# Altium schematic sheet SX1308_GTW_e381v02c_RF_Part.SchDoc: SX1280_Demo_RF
size A2; DrawnBy: Erik Fountain; DocumentNumber: 2; SheetNumber: 2; SheetTotal: 5; PageSetup: Record=PageOptions|CenterHorizontal=True|CenterVertical=True|PrintScale=0.47|XCorrection=1.00|YCorrection=1.00|PrintKind=0|BorderSize=5000000|LeftOffset=0|BottomOffset=0|Orientation=2|PaperLength=1000|PaperWidth=1000|Scale=100|PaperSource=7|PrintQuality=-4|MediaType=1|DitherType=10|PaperKind=Letter|PrintScaleMode=1
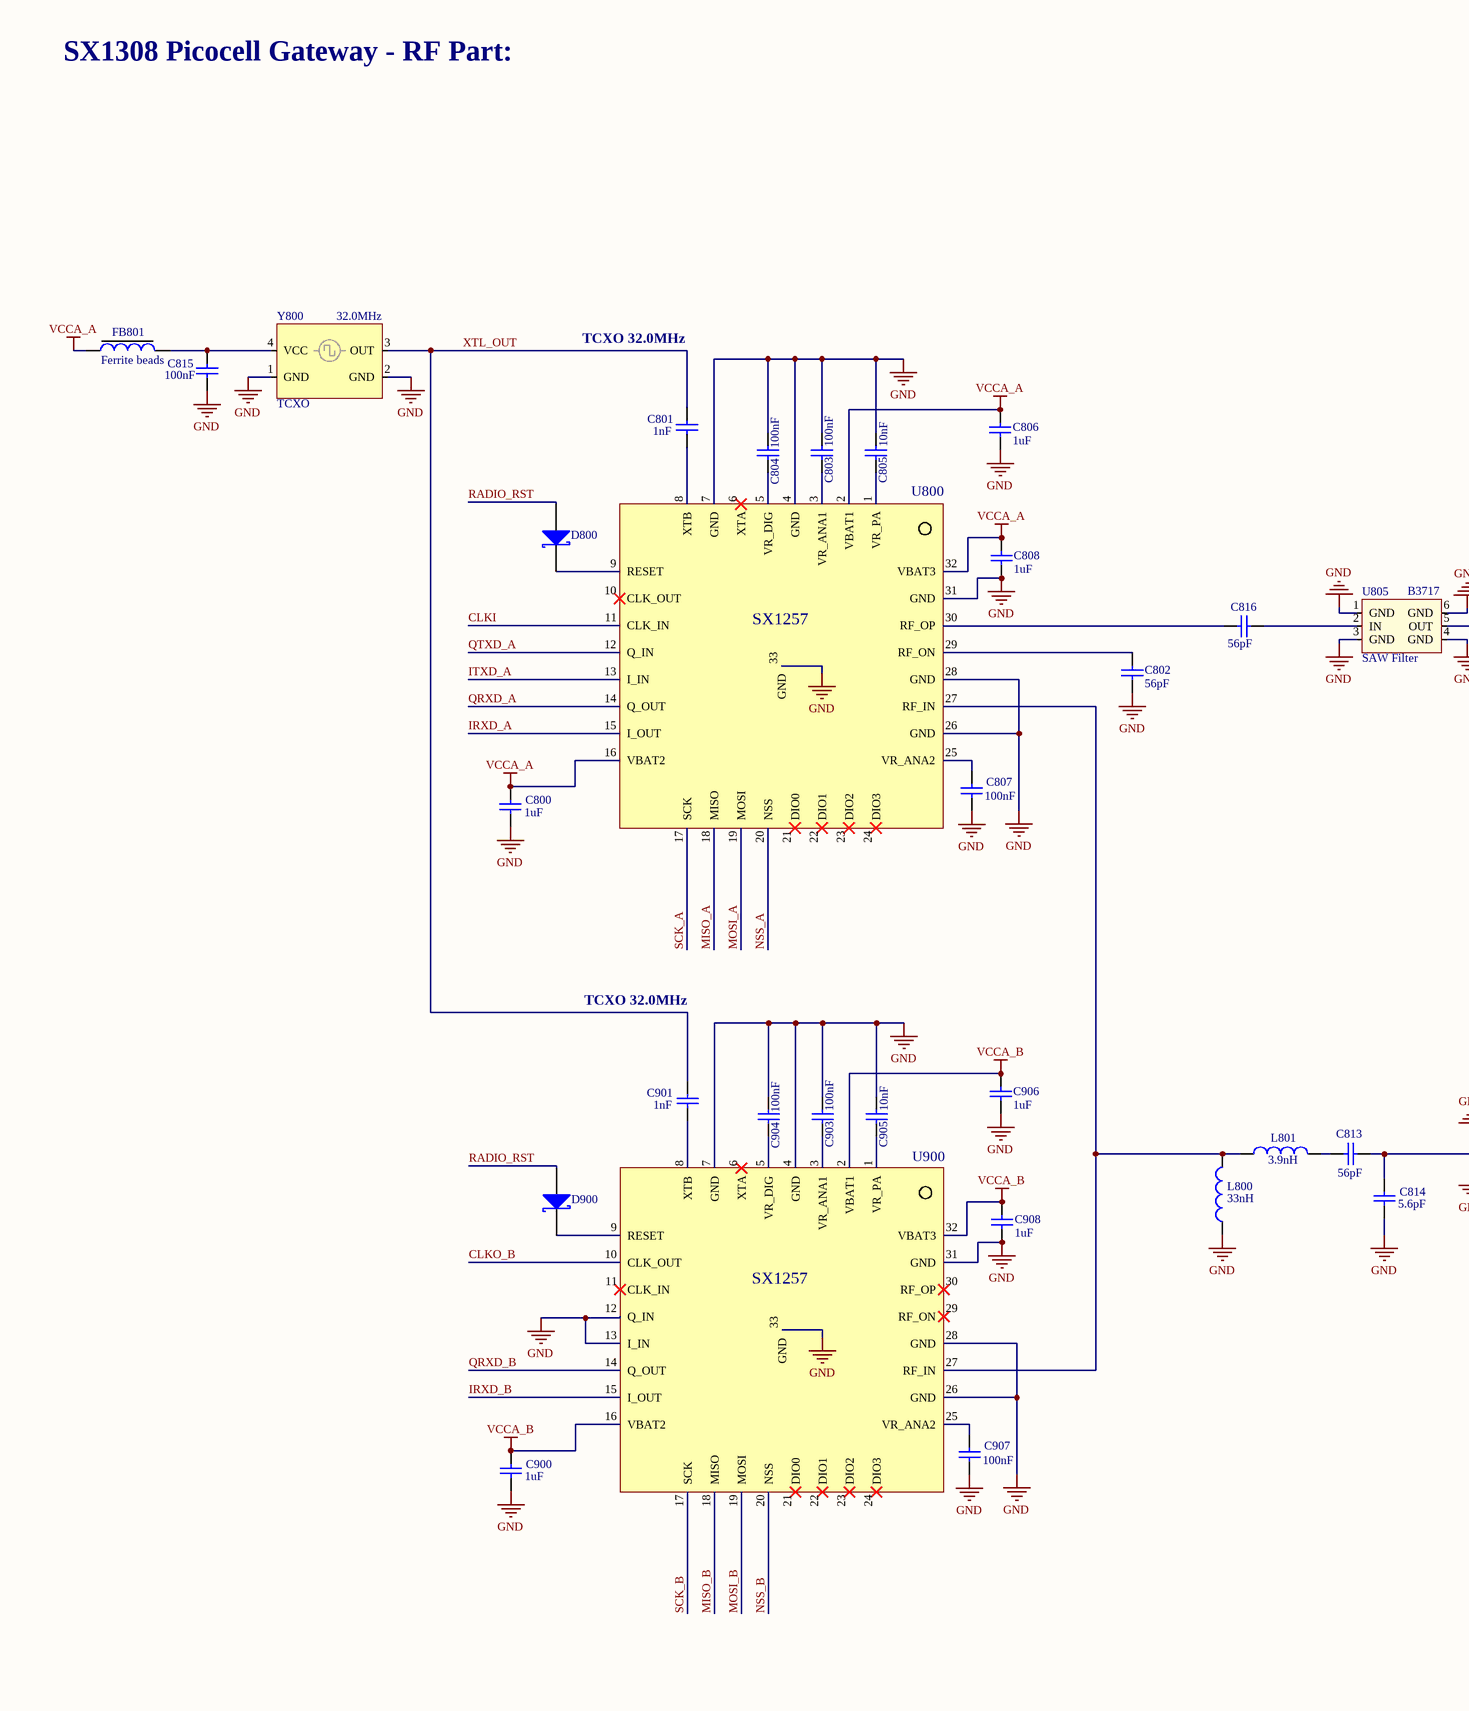
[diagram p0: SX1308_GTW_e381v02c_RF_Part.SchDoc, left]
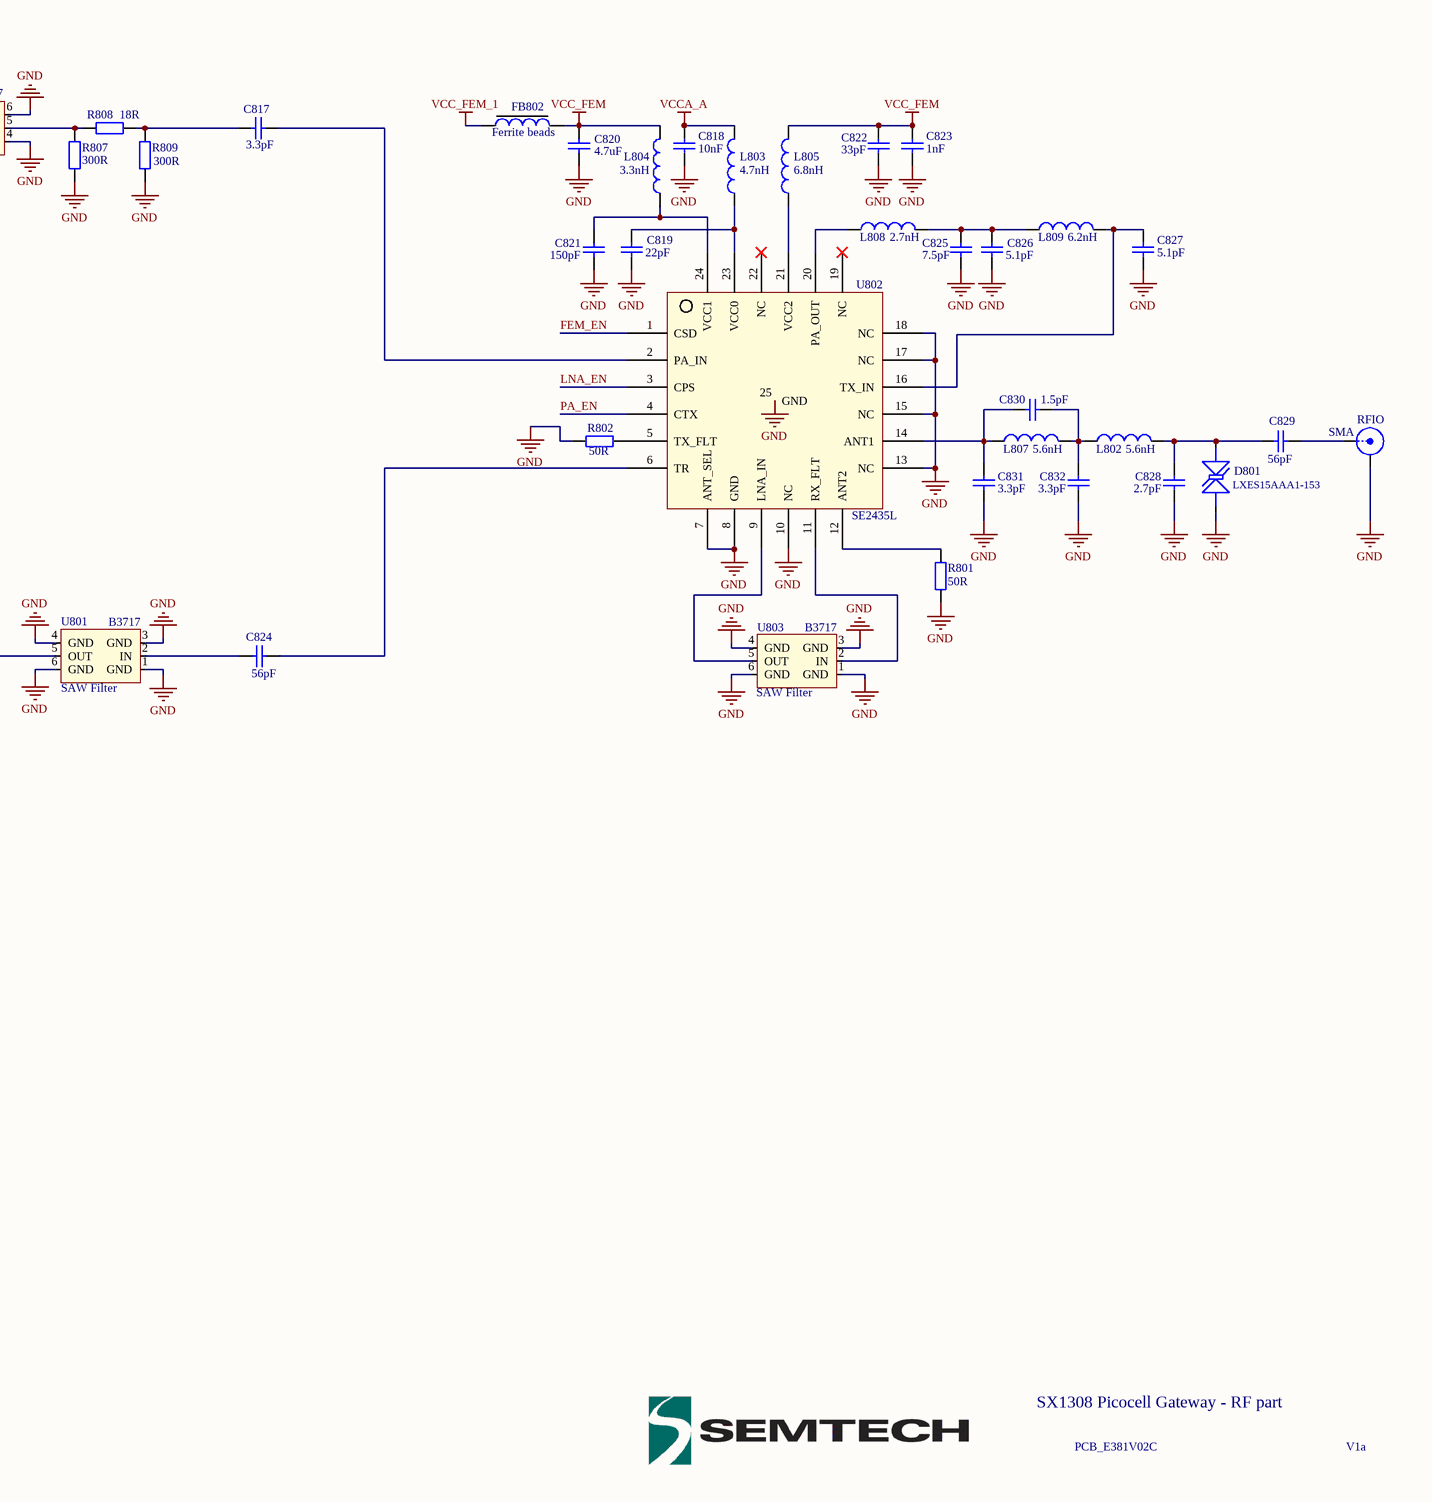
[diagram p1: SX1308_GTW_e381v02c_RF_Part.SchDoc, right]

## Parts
C800  value 1uF  [rlc_603_smd]  (hidden comment: Cap)
C801  value 1nF  [rlc_402_smd]  (hidden comment: Cap)
C802  value 56pF  [rlc_402_smd]  (hidden comment: Cap)
C803  value 100nF  [rlc_402_smd]  (hidden comment: Cap)
C804  value 100nF  [rlc_402_smd]  (hidden comment: Cap)
C805  value 10nF  [rlc_402_smd]  (hidden comment: Cap)
C806  value 1uF  [rlc_603_smd]  (hidden comment: Cap)
C807  value 100nF  [rlc_402_smd]  (hidden comment: Cap)
C808  value 1uF  [rlc_603_smd]  (hidden comment: Cap)
C813  value 56pF  [rlc_402_smd]  (hidden comment: Cap)
C814  value 5.6pF  [rlc_402_smd]  (hidden comment: Cap)
C815  value 100nF  [rlc_402_smd]  (hidden comment: Cap)
C816  value 56pF  [rlc_402_smd]  (hidden comment: Cap)
C817  value 3.3pF  [rlc_402_smd]  (hidden comment: Cap)
C818  value 10nF  [rlc_402_smd]  (hidden comment: Cap)
C819  value 22pF  [rlc_402_smd]  (hidden comment: Cap)
C820  value 4.7uF  [rlc_603_smd]  (hidden comment: Cap)
C821  value 150pF  [rlc_402_smd]  (hidden comment: Cap)
C822  value 33pF  [rlc_402_smd]  (hidden comment: Cap)
C823  value 1nF  [rlc_402_smd]  (hidden comment: Cap)
C824  value 56pF  [rlc_402_smd]  (hidden comment: Cap)
C825  value 7.5pF  [rlc_402_smd]  (hidden comment: Cap)
C826  value 5.1pF  [rlc_402_smd]  (hidden comment: Cap)
C827  value 5.1pF  [rlc_402_smd]  (hidden comment: Cap)
C828  value 2.7pF  [rlc_402_smd]  (hidden comment: Cap)
C829  value 56pF  [rlc_402_smd]  (hidden comment: Cap)
C830  value 1.5pF  [rlc_402_smd]  (hidden comment: Cap)
C831  value 3.3pF  [rlc_402_smd]  (hidden comment: Cap)
C832  value 3.3pF  [rlc_402_smd]  (hidden comment: Cap)
C900  value 1uF  [rlc_603_smd]  (hidden comment: Cap)
C901  value 1nF  [rlc_402_smd]  (hidden comment: Cap)
C903  value 100nF  [rlc_402_smd]  (hidden comment: Cap)
C904  value 100nF  [rlc_402_smd]  (hidden comment: Cap)
C905  value 10nF  [rlc_402_smd]  (hidden comment: Cap)
C906  value 1uF  [rlc_603_smd]  (hidden comment: Cap)
C907  value 100nF  [rlc_402_smd]  (hidden comment: Cap)
C908  value 1uF  [rlc_603_smd]  (hidden comment: Cap)
D800  D Schottky  [SOD523]  (value not drawn)
D801  Type: LXES15AAA1-153  [SLP1006P2T]  (hidden comment: RClamp0531T)
D900  D Schottky  [SOD523]  (value not drawn)
FB801  Ferrite beads  [rlc_402_smd]
FB802  Ferrite beads  [rlc_603_smd]
L800  value 33nH  [rlc_402_smd]  (hidden comment: Inductor)
L801  value 3.9nH  [rlc_402_smd]  (hidden comment: Inductor)
L802  value 5.6nH  [rlc_402_smd]  (hidden comment: Inductor)
L803  value 4.7nH  [rlc_402_smd]  (hidden comment: Inductor)
L804  value 3.3nH  [rlc_402_smd]  (hidden comment: Inductor)
L805  value 6.8nH  [rlc_402_smd]  (hidden comment: Inductor)
L807  value 5.6nH  [rlc_402_smd]  (hidden comment: Inductor)
L808  value 2.7nH  [rlc_402_smd]  (hidden comment: Inductor)
L809  value 6.2nH  [rlc_402_smd]  (hidden comment: Inductor)
R801  value 50R  [rlc_402_smd]  (hidden comment: Resistor)
R802  value 50R  [rlc_402_smd]  (hidden comment: Resistor)
R807  value 300R  [rlc_402_smd]  (hidden comment: Resistor)
R808  value 18R  [rlc_402_smd]  (hidden comment: Resistor)
R809  value 300R  [rlc_402_smd]  (hidden comment: Resistor)
RFIO  SMA  [SMA_end_launch_1.6mm_6.35mm]
U800  SX1257  [vqfn32_5x5mm]
U801  SAW Filter  value B3717  [DCC6C_3.0x3.0mm]
U802  SE2435L  [vqfn24_4x4mm RF]
U803  SAW Filter  value B3717  [DCC6C_3.0x3.0mm]
U805  SAW Filter  value B3717  [DCC6C_3.0x3.0mm]
U900  SX1257  [vqfn32_5x5mm]
Y800  TCXO  value 32.0MHz  [TCXO 2.0x1.6mm]

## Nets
GND: C800.1 C802.2 C803.1 C804.2 C805.2 C806.1 C807.1 C808.1 C814.2 C815.1 C818.1 C819.1 C820.1 C821.1 C822.1 C823.1 C825.1 C826.1 C827.1 C828.2 C831.1 C832.2 C900.1 C903.1 C904.2 C905.2 C906.1 C907.1 C908.1 D801.2(K) L800.1 R801.2 R802.2 R807.1 R809.1 RFIO.2(GND) U800.4(GND) U800.7(GND) U800.26(GND) U800.28(GND) U800.31(GND) U800.33(GND) U801.1(GND) U801.3(GND) U801.4(GND) U801.6(GND) U802.7(ANT_SEL) U802.8(GND) U802.10(NC) U802.13(NC) U802.15(NC) U802.17(NC) U802.18(NC) U802.25(GND) U803.1(GND) U803.3(GND) U803.4(GND) U803.6(GND) U805.1(GND) U805.3(GND) U805.4(GND) U805.6(GND) U900.4(GND) U900.7(GND) U900.12(Q_IN) U900.13(I_IN) U900.26(GND) U900.28(GND) U900.31(GND) U900.33(GND) Y800.1(GND) Y800.2(GND)
VCC_FEM: C820.2 C822.2 C823.2 FB802.2 L804.2 L805.2
VCC_FEM_1: FB802.1
VCCA_A: C800.2 C806.2 C808.2 C818.2 FB801.1 L803.2 U800.2(VBAT1) U800.16(VBAT2) U800.32(VBAT3)
VCCA_B: C900.2 C906.2 C908.2 U900.2(VBAT1) U900.16(VBAT2) U900.32(VBAT3)
CLKI: U800.11(CLK_IN)
CLKO_B: U900.10(CLK_OUT)
FEM_EN: U802.1(CSD)
IRXD_A: U800.15(I_OUT)
IRXD_B: U900.15(I_OUT)
ITXD_A: U800.13(I_IN)
LNA_EN: U802.3(CPS)
MISO_A: U800.18(MISO)
MISO_B: U900.18(MISO)
MOSI_A: U800.19(MOSI)
MOSI_B: U900.19(MOSI)
NSS_A: U800.20(NSS)
NSS_B: U900.20(NSS)
PA_EN: U802.4(CTX)
QRXD_A: U800.14(Q_OUT)
QRXD_B: U900.14(Q_OUT)
QTXD_A: U800.12(Q_IN)
RADIO_RST: D800.2(A) D900.2(A)
SCK_A: U800.17(SCK)
SCK_B: U900.17(SCK)
XTL_OUT: C801.1 C901.2 Y800.3(OUT)
NetC801_2: C801.2 U800.8(XTB)
NetC802_1: C802.1 U800.29(RF_ON)
NetC803_2: C803.2 U800.3(VR_ANA1)
NetC804_1: C804.1 U800.5(VR_DIG)
NetC805_1: C805.1 U800.1(VR_PA)
NetC807_2: C807.2 U800.25(VR_ANA2)
NetC813_1: C813.1 L801.2
NetC813_2: C813.2 C814.1 U801.5(OUT)
NetC815_2: C815.2 FB801.2 Y800.4(VCC)
NetC816_1: C816.1 U800.30(RF_OP)
NetC816_2: C816.2 U805.2(IN)
NetC817_1: C817.1 R808.2 R809.2
NetC817_2: C817.2 U802.2(PA_IN)
NetC819_2: C819.2 L803.1 U802.23(VCC0)
NetC821_2: C821.2 L804.1 U802.24(VCC1)
NetC824_1: C824.1 U801.2(IN)
NetC824_2: C824.2 U802.6(TR)
NetC825_2: C825.2 C826.2 L808.2 L809.1
NetC827_2: C827.2 L809.2 U802.16(TX_IN)
NetC828_1: C828.1 C829.1 D801.1(A) L802.2
NetC829_2: C829.2 RFIO.1(Signal)
NetC830_1: C830.1 C832.1 L802.1 L807.2
NetC830_2: C830.2 C831.2 L807.1 U802.14(ANT1)
NetC901_1: C901.1 U900.8(XTB)
NetC903_2: C903.2 U900.3(VR_ANA1)
NetC904_1: C904.1 U900.5(VR_DIG)
NetC905_1: C905.1 U900.1(VR_PA)
NetC907_2: C907.2 U900.25(VR_ANA2)
NetD800_1: D800.1(K) U800.9(RESET)
NetD900_1: D900.1(K) U900.9(RESET)
NetL800_2: L800.2 L801.1 U800.27(RF_IN) U900.27(RF_IN)
NetL805_1: L805.1 U802.21(VCC2)
NetL808_1: L808.1 U802.20(PA_OUT)
NetR801_1: R801.1 U802.12(ANT2)
NetR802_1: R802.1 U802.5(TX_FLT)
NetR807_2: R807.2 R808.1 U805.5(OUT)
NetU802_9: U802.9(LNA_IN) U803.5(OUT)
NetU802_11: U802.11(RX_FLT) U803.2(IN)

Not connected (* = marked no-connect by the designer): U800 6(XTA)* 10(CLK_OUT)* 21(DIO0)* 22(DIO1)* 23(DIO2)* 24(DIO3)*; U802 19(NC)* 22(NC)*; U900 6(XTA)* 11(CLK_IN)* 21(DIO0)* 22(DIO1)* 23(DIO2)* 24(DIO3)* 29(RF_ON)* 30(RF_OP)*

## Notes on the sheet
- SX1308 Picocell Gateway - RF Part:
- TCXO 32.0MHz
- SX1308 Picocell Gateway - RF part
- PCB_E381V02C
- V1a

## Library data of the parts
C800-C808 C813-C832 C900 C901 C903-C908 = Cap: Capacitor SMD
D800 D900 = D Schottky: Schottky Diode
D801 = RClamp0531T: Ultra Low Capacitance 1-line ESD Protection
FB801 FB802 = Ferrite beads: Value: VAL?
L800-L805 L807-L809 = Inductor: Code_IEC: 1005
R801 R802 R807-R809 = Resistor: Resistor SMD - IEC symbol version
RFIO = SMA: SMA Straight Connector
U800 U900 = SX1257: SX1257 RF Front-End Transceiver - I/Q New Pinout
U801 U803 U805 = SAW Filter: SAW Filter - Bandpass - TEMEX type
U802 = SE2435L: SE2435L - Skyworks High Power RF Front End Module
